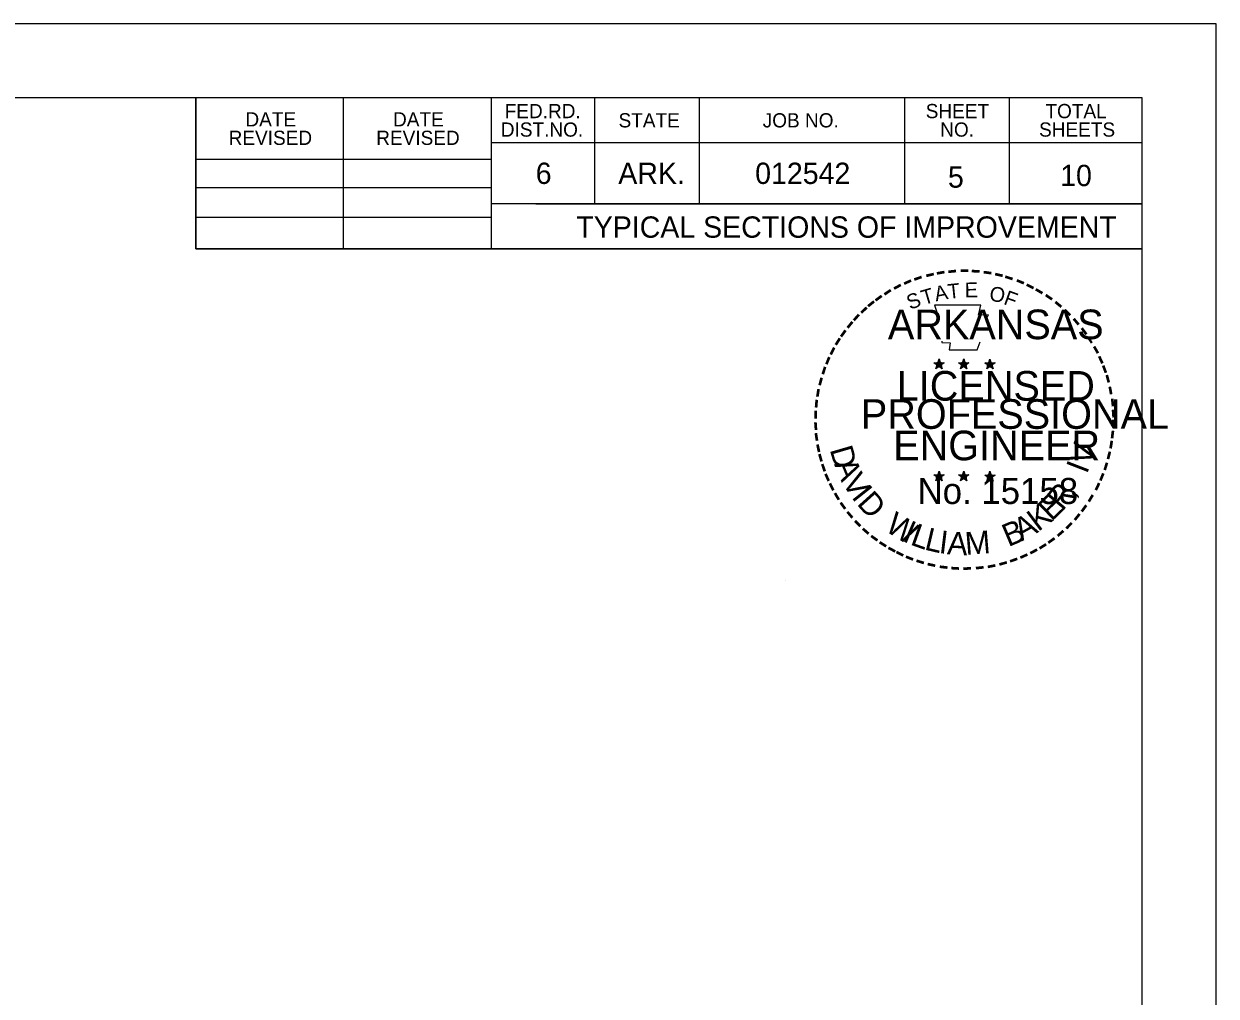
# Model space of a CAD drawing. Extents: x 34757 to 38214, y 51436 to 59430.
# Drawn here: x 36054.1 to 36456.6, y 54141.3 to 54469.6 of the extents above; entities that cross this region are included whole.
import ezdxf

# ---------------------------------------------------------------- set-up
doc = ezdxf.new("R2010")
doc.units = 0
for name, color, linetype in [('Default', 7, 'Continuous'), ('DSN_DRFT_Junk-No-Plot', 7, 'Continuous'), ('R_Border PE', 7, 'Continuous'), ('R_No Plot', 7, 'Continuous'), ('SHET_Annotations', 7, 'Continuous'), ('SHET_Border-Lines', 7, 'Continuous'), ('SHET_Border-Text', 7, 'Continuous'), ('SHET_Stamp-Prelim', 7, 'Continuous')]:
    doc.layers.add(name, color=color, linetype=linetype)

msp = doc.modelspace()

# ---------------------------------------------------------------- linework, layer by layer
at = {"layer": 'Default'}
msp.add_lwpolyline([(34756.64, 54469.61), (34756.64, 53369.61), (36456.64, 53369.61), (36456.64, 54469.61)], close=True, dxfattribs=at)
at = {"layer": 'DSN_DRFT_Junk-No-Plot'}
msp.add_lwpolyline([(34756.64, 54469.61), (34756.64, 53369.61), (36456.64, 53369.61), (36456.64, 54469.61)], close=True, dxfattribs=at)
at = {"layer": 'R_Border PE'}
for p, q in [((36363.1, 54356.44), (36362.89, 54355.18)), ((36363.1, 54354.61), (36363.1, 54356.44)), ((36363.1, 54356.44), (36363.34, 54355.19)), ((36371.45, 54356.44), (36371.24, 54355.18)), ((36371.45, 54354.61), (36371.45, 54356.44)), ((36371.45, 54356.44), (36371.69, 54355.19)), ((36380.27, 54356.38), (36380.06, 54355.12)), ((36380.27, 54354.55), (36380.27, 54356.38)), ((36380.27, 54356.38), (36380.51, 54355.13)), ((36361.35, 54355.17), (36363.1, 54354.61)), ((36361.35, 54355.17), (36362.62, 54354.94)), ((36361.35, 54355.17), (36362.54, 54354.56)), ((36362.02, 54353.13), (36363.1, 54354.61)), ((36362.02, 54353.13), (36362.65, 54354.35)), ((36362.02, 54353.13), (36363.09, 54354.21)), ((36364.16, 54353.13), (36363.09, 54354.2)), ((36364.83, 54355.17), (36363.1, 54354.61)), ((36364.16, 54353.13), (36363.1, 54354.61)), ((36364.83, 54355.17), (36363.4, 54354.92)), ((36364.16, 54353.13), (36363.48, 54354.58)), ((36364.83, 54355.17), (36363.81, 54354.66)), ((36369.7, 54355.17), (36371.45, 54354.61)), ((36369.7, 54355.17), (36370.97, 54354.94)), ((36369.7, 54355.17), (36370.89, 54354.56)), ((36370.37, 54353.13), (36371.45, 54354.61)), ((36370.37, 54353.13), (36371, 54354.35)), ((36370.37, 54353.13), (36371.44, 54354.21)), ((36372.51, 54353.13), (36371.44, 54354.2)), ((36373.18, 54355.17), (36371.45, 54354.61)), ((36372.51, 54353.13), (36371.45, 54354.61)), ((36373.18, 54355.17), (36371.75, 54354.92)), ((36372.51, 54353.13), (36371.83, 54354.58)), ((36373.18, 54355.17), (36372.16, 54354.66)), ((36378.52, 54355.11), (36380.27, 54354.55)), ((36378.52, 54355.11), (36379.79, 54354.88)), ((36378.52, 54355.11), (36379.71, 54354.5)), ((36379.19, 54353.07), (36380.27, 54354.55)), ((36379.19, 54353.07), (36379.82, 54354.29)), ((36379.19, 54353.07), (36380.26, 54354.15)), ((36381.33, 54353.07), (36380.26, 54354.14)), ((36382, 54355.11), (36380.27, 54354.55)), ((36381.33, 54353.07), (36380.27, 54354.55)), ((36382, 54355.11), (36380.57, 54354.86)), ((36381.33, 54353.07), (36380.65, 54354.52)), ((36382, 54355.11), (36380.98, 54354.6)), ((36361.33, 54317.3), (36363.08, 54316.75)), ((36361.33, 54317.3), (36362.6, 54317.08)), ((36361.33, 54317.3), (36362.52, 54316.69)), ((36362, 54315.26), (36363.08, 54316.75)), ((36362, 54315.26), (36362.63, 54316.48)), ((36362, 54315.26), (36363.07, 54316.35)), ((36363.08, 54318.57), (36362.87, 54317.31)), ((36364.14, 54315.26), (36363.07, 54316.33)), ((36363.08, 54316.75), (36363.08, 54318.57)), ((36363.08, 54318.57), (36363.32, 54317.32)), ((36364.81, 54317.3), (36363.08, 54316.75)), ((36364.14, 54315.26), (36363.08, 54316.75)), ((36364.81, 54317.3), (36363.38, 54317.06)), ((36364.14, 54315.26), (36363.46, 54316.72)), ((36364.81, 54317.3), (36363.79, 54316.79)), ((36369.68, 54317.3), (36371.42, 54316.75)), ((36369.68, 54317.3), (36370.94, 54317.08)), ((36369.68, 54317.3), (36370.86, 54316.69)), ((36370.34, 54315.26), (36371.42, 54316.75)), ((36370.34, 54315.26), (36370.97, 54316.48)), ((36370.34, 54315.26), (36371.41, 54316.35)), ((36371.42, 54318.57), (36371.22, 54317.31)), ((36372.49, 54315.26), (36371.41, 54316.33)), ((36371.42, 54316.75), (36371.42, 54318.57)), ((36371.42, 54318.57), (36371.67, 54317.32)), ((36373.16, 54317.3), (36371.42, 54316.75)), ((36372.49, 54315.26), (36371.42, 54316.75)), ((36373.16, 54317.3), (36371.73, 54317.06)), ((36372.49, 54315.26), (36371.8, 54316.72)), ((36373.16, 54317.3), (36372.14, 54316.79)), ((36378.51, 54317.25), (36380.26, 54316.7)), ((36378.51, 54317.25), (36379.78, 54317.03)), ((36378.51, 54317.25), (36379.7, 54316.64)), ((36379.18, 54315.21), (36380.26, 54316.7)), ((36379.18, 54315.21), (36379.81, 54316.43)), ((36379.18, 54315.21), (36380.25, 54316.3)), ((36380.26, 54318.52), (36380.05, 54317.26)), ((36381.32, 54315.21), (36380.25, 54316.28)), ((36380.26, 54316.7), (36380.26, 54318.52)), ((36380.26, 54318.52), (36380.5, 54317.27)), ((36381.99, 54317.25), (36380.26, 54316.7)), ((36381.32, 54315.21), (36380.26, 54316.7)), ((36381.99, 54317.25), (36380.56, 54317.01)), ((36381.32, 54315.21), (36380.64, 54316.67)), ((36381.99, 54317.25), (36380.97, 54316.74))]:
    msp.add_line(p, q, dxfattribs=at)
for points in [[(36361.56, 54374.56), (36362.9, 54370.42)], [(36379.11, 54369.95), (36379.82, 54371.37), (36376.4, 54371.25), (36377.14, 54374.56), (36361.56, 54374.56)], [(36364.02, 54362.44), (36364.02, 54362.01), (36366.83, 54361.91), (36366.56, 54359.55), (36375.91, 54359.55), (36376.92, 54362.23)], [(36363.1, 54356.44), (36364.16, 54353.13), (36361.35, 54355.17), (36364.83, 54355.17), (36362.02, 54353.13), (36363.1, 54356.44)], [(36371.45, 54356.44), (36372.51, 54353.13), (36369.7, 54355.17), (36373.18, 54355.17), (36370.37, 54353.13), (36371.45, 54356.44)], [(36380.27, 54356.38), (36381.33, 54353.07), (36378.52, 54355.11), (36382, 54355.11), (36379.19, 54353.07), (36380.27, 54356.38)], [(36363.08, 54318.57), (36364.14, 54315.26), (36361.33, 54317.3), (36364.81, 54317.3), (36362, 54315.26), (36363.08, 54318.57)], [(36371.42, 54318.57), (36372.49, 54315.26), (36369.68, 54317.3), (36373.16, 54317.3), (36370.34, 54315.26), (36371.42, 54318.57)], [(36380.26, 54318.52), (36381.32, 54315.21), (36378.51, 54317.25), (36381.99, 54317.25), (36379.18, 54315.21), (36380.26, 54318.52)]]:
    msp.add_lwpolyline(points, dxfattribs=at)
for centre, radius in [((36363.09, 54354.61), 0.861), ((36363.09, 54354.61), 0.723), ((36363.09, 54354.61), 0.579), ((36363.09, 54354.61), 0.495), ((36363.09, 54354.61), 0.374), ((36363.09, 54354.61), 0.248), ((36363.09, 54354.61), 0.148), ((36371.44, 54354.61), 0.861), ((36371.44, 54354.61), 0.723), ((36371.44, 54354.61), 0.579), ((36371.44, 54354.61), 0.495), ((36371.44, 54354.61), 0.374), ((36371.44, 54354.61), 0.248), ((36371.44, 54354.61), 0.148), ((36380.26, 54354.55), 0.861), ((36380.26, 54354.55), 0.723), ((36380.26, 54354.55), 0.579), ((36380.26, 54354.55), 0.495), ((36380.26, 54354.55), 0.374), ((36380.26, 54354.55), 0.248), ((36380.26, 54354.55), 0.148), ((36363.07, 54316.74), 0.861), ((36363.07, 54316.74), 0.723), ((36363.07, 54316.74), 0.579), ((36363.07, 54316.74), 0.495), ((36363.07, 54316.74), 0.374), ((36363.07, 54316.74), 0.248), ((36363.07, 54316.74), 0.148), ((36371.42, 54316.74), 0.861), ((36371.42, 54316.74), 0.723), ((36371.42, 54316.74), 0.579), ((36371.42, 54316.74), 0.495), ((36371.42, 54316.74), 0.374), ((36371.42, 54316.74), 0.248), ((36371.42, 54316.74), 0.148), ((36380.25, 54316.69), 0.861), ((36380.25, 54316.69), 0.723), ((36380.25, 54316.69), 0.579), ((36380.25, 54316.69), 0.495), ((36380.25, 54316.69), 0.374), ((36380.25, 54316.69), 0.248), ((36380.25, 54316.69), 0.148)]:
    msp.add_circle(centre, radius, dxfattribs=at)
at = {"layer": 'R_No Plot'}
msp.add_line((36311.1, 54281.61), (36311.1, 54281.61), dxfattribs=at)
at = {"layer": 'SHET_Border-Lines'}
for p, q in [((36112.18, 54393.66), (36112.18, 54444.61)), ((36162.01, 54393.66), (36162.01, 54444.61)), ((36211.83, 54444.61), (36211.83, 54393.66)), ((36246.72, 54444.61), (36246.72, 54408.82)), ((36282.11, 54444.61), (36282.11, 54408.82)), ((36351.37, 54444.61), (36351.37, 54408.82)), ((36386.76, 54444.61), (36386.76, 54408.82)), ((36431.64, 54429.45), (36211.83, 54429.45)), ((36431.64, 54429.55), (36431.64, 54429.55)), ((36112.18, 54423.88), (36211.83, 54423.88)), ((36112.18, 54414.29), (36211.83, 54414.29)), ((36431.64, 54408.82), (36211.83, 54408.82)), ((36226.93, 54408.82), (36431.64, 54408.82)), ((36112.18, 54404.29), (36211.83, 54404.29)), ((36431.64, 54393.66), (36112.18, 54393.66))]:
    msp.add_line(p, q, dxfattribs=at)
for points in [[(34756.64, 53369.61), (36456.64, 53369.61), (36456.64, 54469.61), (34756.64, 54469.61)], [(34781.64, 53394.61), (36431.64, 53394.61), (36431.64, 54444.61), (34781.64, 54444.61)], [(36112.18, 54393.66), (36431.64, 54393.66), (36431.64, 54444.61), (36112.18, 54444.61)]]:
    msp.add_lwpolyline(points, close=True, dxfattribs=at)
at = {"layer": 'SHET_Stamp-Prelim'}
msp.add_lwpolyline([(36321.64, 54393.62), (36321.83, 54393.62), (36321.83, 54393.66), (36321.64, 54393.66)], close=True, dxfattribs=at)

# ---------------------------------------------------------------- texts
at = {"layer": 'R_Border PE'}
for s, height, rotation, p in [('-', 8, 19.1761, (36355.29, 54380.19)), ('-', 8, 13.6302, (36359.04, 54381.4)), ('-', 8, 10.2193, (36362.43, 54382.21)), ('-', 8, 5.8968, (36366.08, 54382.76)), ('-', 8, 0.1862, (36369.94, 54383.12)), ('-', 8, 357.743, (36373.55, 54383.05)), ('-', 8, 352.1617, (36377.27, 54382.77)), ('-', 8, 347.2049, (36380.87, 54382.2)), ('-', 8, 342.3362, (36384.04, 54381.43)), ('-', 8, 28.7918, (36348.96, 54377.26)), ('-', 8, 24.3072, (36352.12, 54378.85)), ('T', 5, 16.4036, (36357.9, 54374.6)), ('A', 5, 11.2132, (36362.03, 54375.86)), ('T', 5, 6.0228, (36366.27, 54376.69)), ('E', 5, 0.8323, (36371.8, 54377.24)), ('O', 5, 350.4515, (36379.82, 54376.19)), ('-', 8, 337.8551, (36387.72, 54380.31)), ('-', 8, 334.1211, (36390.87, 54378.96)), ('-', 8, 329.6409, (36393.77, 54377.54)), ('-', 8, 38.9507, (36340.7, 54371.55)), ('-', 8, 36.2317, (36343.08, 54373.44)), ('-', 8, 34.0636, (36345.97, 54375.41)), ('S', 5, 21.594, (36353.33, 54372.95)), ('F', 5, 340.0707, (36384.59, 54375.05)), ('-', 8, 325.8627, (36396.98, 54375.74)), ('-', 8, 42.9622, (36338.54, 54369.46)), ('-', 8, 320.5297, (36400.03, 54373.61)), ('-', 8, 315.5786, (36403.03, 54371.17)), ('-', 8, 50.6142, (36334.28, 54364.64)), ('-', 8, 48.4231, (36336.3, 54367.07)), ('-', 8, 309.8797, (36405.87, 54368.42)), ('-', 8, 54.2325, (36332.22, 54361.81)), ('-', 8, 306.6522, (36408.5, 54365.41)), ('-', 8, 62.8713, (36329.03, 54356.1)), ('-', 8, 58.0706, (36330.59, 54359.17)), ('-', 7, 303.6753, (36410.93, 54362.57)), ('-', 8, 299.6684, (36412.52, 54359.53)), ('-', 8, 67.7743, (36327.73, 54353.05)), ('-', 8, 294.6628, (36414.14, 54356.47)), ('-', 8, 72.3945, (36326.64, 54349.9)), ('-', 8, 290.5728, (36415.43, 54353.59)), ('-', 8, 75.461, (36325.65, 54346.33)), ('-', 8, 285.1233, (36416.6, 54350.69)), ('-', 8, 81.2013, (36324.99, 54342.76)), ('-', 8, 280.5493, (36417.6, 54346.98)), ('-', 8, 85.1863, (36324.61, 54339.31)), ('-', 8, 276.5962, (36418.41, 54343.14)), ('-', 8, 89.0622, (36324.49, 54335.8)), ('-', 8, 274.3301, (36418.71, 54339.53)), ('-', 8, 269.9407, (36418.88, 54336.37)), ('-', 8, 94.1959, (36324.66, 54332.18)), ('-', 8, 263.5172, (36418.78, 54333.04)), ('-', 8, 98.9479, (36325.02, 54328.84)), ('V', 7.7, 72.6573, (36414.1, 54320.07)), ('-', 8, 260.9953, (36418.43, 54329.77)), ('-', 8, 101.7149, (36325.7, 54325.18)), ('-', 8, 105.4578, (36326.51, 54322.2)), ('D', 7.7, 286.2848, (36326.14, 54325.87)), ('-', 8, 255.7626, (36417.88, 54326.38)), ('-', 8, 109.0874, (36327.58, 54319.05)), ('A', 7.7, 292.7835, (36327.61, 54320.86)), ('I', 7.7, 69.0301, (36412.99, 54317.37)), ('-', 8, 252.8681, (36416.97, 54322.78)), ('-', 8, 114.0643, (36328.85, 54316.07)), ('V', 7.7, 300.7936, (36330.18, 54314.96)), ('-', 8, 247.8887, (36415.86, 54319.41)), ('-', 8, 115.7289, (36330.38, 54312.98)), ('I', 7.7, 308.3502, (36333.33, 54309.78)), ('D', 7.7, 311.9774, (36335.08, 54307.45)), ('R', 7.7, 50.3651, (36404.74, 54304.93)), ('-', 8, 244.6197, (36414.55, 54316.27)), ('-', 8, 120.4471, (36332.16, 54310.05)), ('-', 8, 125.8934, (36334.18, 54307.24)), ('K', 7.7, 36.9143, (36396.53, 54297.94)), ('E', 7.7, 44.0175, (36401.07, 54301.39)), (',', 7.7, 57.4684, (36408.36, 54309.34)), ('-', 8, 239.0712, (36412.58, 54312.51)), ('-', 8, 130.7181, (36336.49, 54304.48)), ('W', 7.7, 328.0731, (36344.48, 54298.62)), ('-', 8, 231.2538, (36408.42, 54306.41)), ('-', 8, 233.8452, (36410.57, 54309.24)), ('-', 8, 134.2238, (36339.07, 54301.76)), ('I', 7.7, 336.6877, (36350.41, 54295.07)), ('L', 7.7, 340.3149, (36353.06, 54293.85)), ('B', 7.7, 22.8589, (36386.46, 54292.88)), ('A', 7.7, 28.9042, (36390.94, 54294.75)), ('-', 8, 225.7653, (36406.02, 54303.59)), ('-', 8, 138.9338, (36341.7, 54299.44)), ('-', 8, 144.6463, (36344.48, 54297.41)), ('L', 7.7, 346.6625, (36357.86, 54292.13)), ('I', 7.7, 353.0101, (36362.82, 54290.95)), ('A', 7.7, 356.6373, (36365.7, 54290.52)), ('M', 7.7, 4.6473, (36372.13, 54290.23)), ('-', 8, 215.7363, (36400.67, 54298.69)), ('-', 8, 221.0851, (36403.41, 54301.05)), ('-', 8, 148.0898, (36347.28, 54295.55)), ('-', 8, 151.5704, (36350.18, 54293.93)), ('-', 8, 154.6002, (36352.79, 54292.69)), ('-', 8, 207.3568, (36395.21, 54295.02)), ('-', 8, 212.2491, (36398, 54296.75)), ('-', 8, 158.5612, (36355.91, 54291.42)), ('-', 8, 162.7983, (36359.34, 54290.36)), ('-', 8, 167.5555, (36362.92, 54289.54)), ('-', 8, 195.4743, (36385.61, 54290.85)), ('-', 8, 199.4643, (36388.93, 54292.04)), ('-', 8, 204.2516, (36392.09, 54293.43)), ('-', 8, 173.1155, (36366.78, 54288.99)), ('-', 8, 176.5183, (36370.52, 54288.72)), ('-', 8, 181.5918, (36374.24, 54288.82)), ('-', 8, 185.8167, (36378.28, 54289.2)), ('-', 8, 191.2858, (36381.96, 54289.86))]:
    msp.add_text(s, height=height, rotation=rotation, dxfattribs=at).set_placement(p)
for s, height, p in [('ARKANSAS', 10, (36345.82, 54363.12)), ('LICENSED', 10, (36348.81, 54342.37)), ('PROFESSIONAL', 10, (36336.69, 54332.85)), ('ENGINEER', 10, (36347.62, 54322.23)), ('No. 15158', 8.785, (36355.83, 54307.47)), ('AAMU', 0.0001, (36371.09, 54290.2))]:
    msp.add_text(s, height=height, dxfattribs=at).set_placement(p)
at = {"layer": 'SHET_Annotations'}
for s, p in [('6', (36226.93, 54415.54)), ('ARK.', (36254.8, 54415.54)), ('012542', (36301.01, 54415.54)), ('5', (36366.09, 54414.29)), ('10', (36403.98, 54414.8)), ('TYPICAL SECTIONS OF IMPROVEMENT', (36240.64, 54397.38))]:
    msp.add_text(s, height=7.2, dxfattribs=at).set_placement(p)
at = {"layer": 'SHET_Border-Text'}
for s, p in [('FED.RD.', (36216.44, 54437.75)), ('SHEET', (36358.59, 54437.75)), ('TOTAL', (36399, 54437.75)), ('DATE', (36128.93, 54434.96)), ('DATE', (36178.76, 54434.96)), ('STATE', (36254.89, 54434.63)), ('JOB NO.', (36303.56, 54434.63)), ('REVISED', (36123.25, 54428.72)), ('REVISED', (36173.08, 54428.72)), ('DIST.NO.', (36215.14, 54431.51)), ('NO.', (36363.48, 54431.51)), ('SHEETS', (36396.85, 54431.51))]:
    msp.add_text(s, height=4.8, dxfattribs=at).set_placement(p)
at = {"layer": 'SHET_Stamp-Prelim'}
for s, height, p in [('PRELIMINARY', 0.013, (36321.66, 54393.64)), ('SUBJECT TO REVISION', 0.009, (36321.67, 54393.63))]:
    msp.add_text(s, height=height, dxfattribs=at).set_placement(p)

doc.saveas('drawing.dxf')
